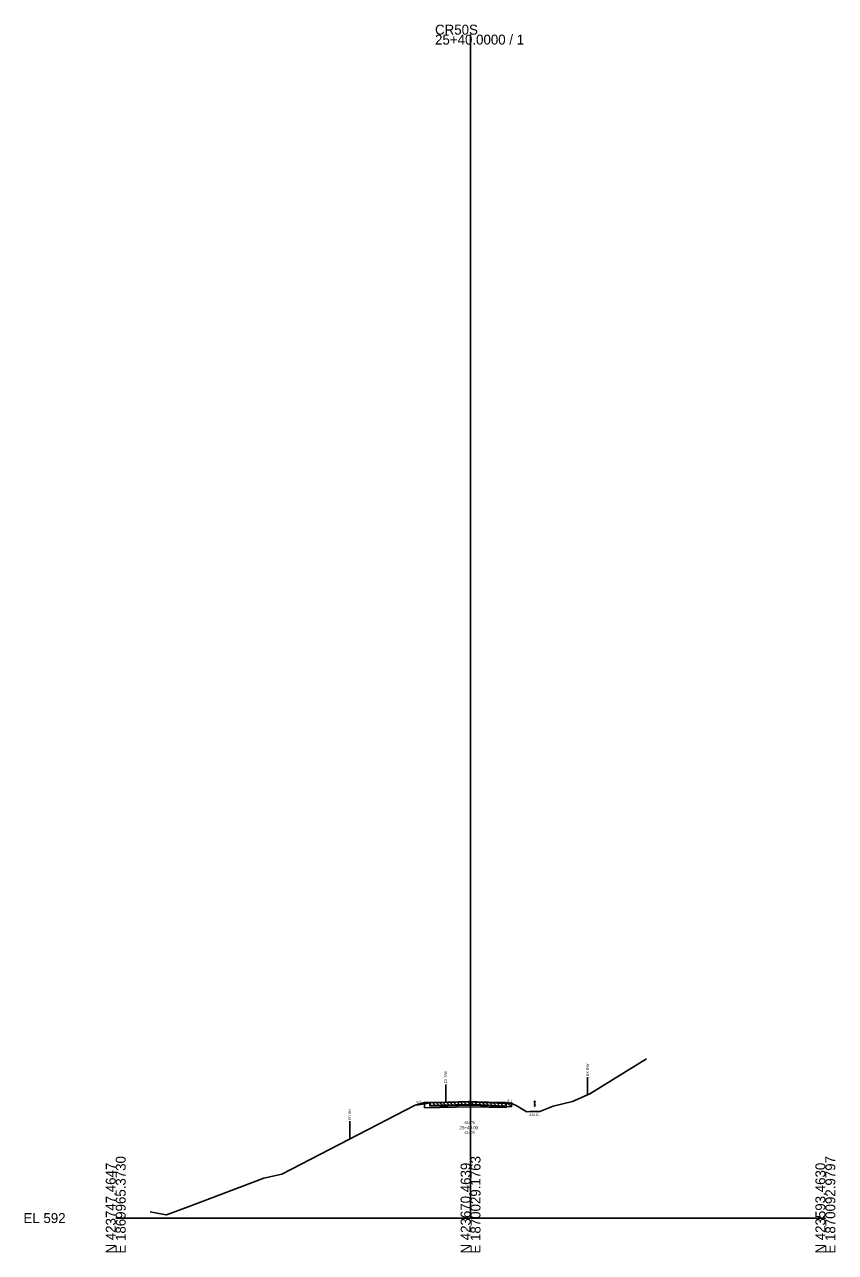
# Model space of a CAD drawing. Extents: x 1866342 to 1870084, y 421982 to 426629.
# Drawn here: x 1867342.4 to 1867571, y 422480.9 to 422827.1 of the extents above; entities that cross this region are included whole.
import ezdxf

# ---------------------------------------------------------------- set-up
doc = ezdxf.new("R2010")
doc.units = 0
for name, color, linetype in [('DR_P_Flow_Arrow', 7, 'Continuous'), ('GK_Cells', 7, 'Continuous'), ('RW_P_Esmt_SH', 7, 'Continuous'), ('RW_X_Fee_RW', 7, 'Continuous'), ('XS_P_Annotation', 7, 'Continuous'), ('XS_P_Earthwork_Shapes', 7, 'Continuous'), ('XS_P_Finished_Grade', 7, 'Continuous'), ('XS_P_Subgrade', 7, 'Continuous'), ('XS_X_Ground_Line', 7, 'Continuous'), ('XS_X_Pavt', 7, 'Continuous')]:
    doc.layers.add(name, color=color, linetype=linetype)

msp = doc.modelspace()

# ---------------------------------------------------------------- linework, layer by layer
at = {"layer": 'DR_P_Flow_Arrow'}
for p, q in [((1867486.09, 422523.31), (1867486.2, 422523.71)), ((1867486.31, 422523.31), (1867486.09, 422523.31)), ((1867486.2, 422523.71), (1867486.31, 422523.31))]:
    msp.add_line(p, q, dxfattribs=at)
msp.add_spline([(1867486.2, 422523.31), (1867486.2, 422523.29), (1867486.16, 422523.13), (1867486.13, 422523.02), (1867486.31, 422522.81), (1867486.1, 422522.57), (1867486.31, 422522.29), (1867486.2, 422522.23), (1867486.2, 422521.96)], degree=3, dxfattribs=at)
at = {"layer": 'GK_Cells'}
for p, q in [((1867468.12, 422490.63), (1867468.12, 422824.29)), ((1867368.12, 422490.63), (1867468.12, 422490.63)), ((1867468.12, 422490.63), (1867568.12, 422490.63))]:
    msp.add_line(p, q, dxfattribs=at)
at = {"layer": 'RW_P_Esmt_SH'}
msp.add_line((1867434.12, 422512.95), (1867434.12, 422517.95), dxfattribs=at)
at = {"layer": 'RW_X_Fee_RW'}
for p, q in [((1867461.12, 422523.28), (1867461.12, 422528.28)), ((1867501.12, 422525.39), (1867501.12, 422530.39))]:
    msp.add_line(p, q, dxfattribs=at)
at = {"layer": 'XS_P_Annotation'}
for q in [(1867455.12, 422523.19), (1867478.12, 422523.23)]:
    msp.add_line((1867468.12, 422523.39), q, dxfattribs=at)
at = {"layer": 'XS_P_Earthwork_Shapes'}
for p, q in [((1867455.12, 422523.19), (1867452.53, 422522.42)), ((1867455.12, 422522.85), (1867455.12, 422523.19)), ((1867455.12, 422522.85), (1867455.12, 422521.75)), ((1867455.12, 422521.75), (1867468.12, 422521.96)), ((1867468.12, 422521.96), (1867478.12, 422521.8)), ((1867479.79, 422522.89), (1867478.12, 422523.23)), ((1867478.12, 422523.23), (1867478.12, 422522.96)), ((1867478.12, 422521.8), (1867478.12, 422522.96)), ((1867478.12, 422522.96), (1867478.12, 422522.22)), ((1867478.12, 422522.96), (1867479.79, 422522.89))]:
    msp.add_line(p, q, dxfattribs=at)
for points in [[(1867452.53, 422522.42), (1867453.49, 422522.6), (1867455.12, 422522.85)], [(1867478.12, 422522.22), (1867468.82, 422522.62), (1867467.55, 422522.68), (1867456.78, 422522.36), (1867456.76, 422523.1), (1867455.12, 422522.85)], [(1867456.76, 422523.1), (1867467.55, 422523.42), (1867478.12, 422522.96)], [(1867456.78, 422522.36), (1867467.55, 422522.68), (1867478.09, 422522.22)]]:
    msp.add_lwpolyline(points, dxfattribs=at)
at = {"layer": 'XS_P_Finished_Grade'}
for p, q in [((1867455.12, 422523.19), (1867452.53, 422522.42)), ((1867478.12, 422523.23), (1867479.79, 422522.89))]:
    msp.add_line(p, q, dxfattribs=at)
at = {"layer": 'XS_P_Subgrade'}
for p, q in [((1867455.12, 422523.19), (1867455.12, 422521.75)), ((1867468.12, 422521.96), (1867455.12, 422521.75)), ((1867468.12, 422521.96), (1867478.12, 422521.8)), ((1867478.12, 422523.23), (1867478.12, 422521.8))]:
    msp.add_line(p, q, dxfattribs=at)
at = {"layer": 'XS_X_Ground_Line'}
msp.add_lwpolyline([(1867377.84, 422492.38), (1867381.77, 422491.67), (1867382.43, 422491.57), (1867388.57, 422493.82), (1867409.84, 422501.89), (1867414.94, 422503.03), (1867428.35, 422509.98), (1867452.53, 422522.42), (1867453.49, 422522.6), (1867456.76, 422523.1), (1867464.03, 422523.29), (1867467.55, 422523.42), (1867468.12, 422523.39), (1867471.23, 422523.27), (1867479.79, 422522.89), (1867480.15, 422522.76), (1867480.96, 422522.39), (1867483.3, 422520.98), (1867484.01, 422520.63), (1867484.83, 422520.64), (1867487.65, 422520.65), (1867491.37, 422522.21), (1867496.82, 422523.51), (1867501.72, 422525.65), (1867517.74, 422535.57)], dxfattribs=at)
at = {"layer": 'XS_X_Pavt'}
for p, q in [((1867456.61, 422523.16), (1867456.61, 422523.41)), ((1867456.61, 422523.16), (1867461.69, 422523.29)), ((1867456.61, 422522.16), (1867456.61, 422523.16)), ((1867456.61, 422522.16), (1867461.69, 422522.29)), ((1867458.41, 422522.21), (1867457.44, 422523.18)), ((1867459.39, 422522.23), (1867458.41, 422523.21)), ((1867460.36, 422522.26), (1867459.39, 422523.23)), ((1867461.33, 422522.29), (1867460.36, 422523.26)), ((1867462.3, 422522.32), (1867461.33, 422523.29)), ((1867461.69, 422523.29), (1867467.53, 422523.51)), ((1867461.69, 422522.29), (1867467.53, 422522.51)), ((1867463.27, 422522.35), (1867462.3, 422523.32)), ((1867464.24, 422522.39), (1867463.27, 422523.35)), ((1867465.2, 422522.42), (1867464.24, 422523.39)), ((1867466.17, 422522.45), (1867465.2, 422523.42)), ((1867467.14, 422522.48), (1867466.17, 422523.45)), ((1867468.14, 422522.48), (1867467.14, 422523.48)), ((1867467.53, 422523.51), (1867468.12, 422523.48)), ((1867467.53, 422522.51), (1867468.12, 422522.48)), ((1867468.12, 422523.48), (1867473.64, 422523.26)), ((1867468.12, 422522.48), (1867473.64, 422522.26)), ((1867469.18, 422522.44), (1867468.14, 422523.48)), ((1867470.23, 422522.4), (1867469.18, 422523.44)), ((1867471.27, 422522.35), (1867470.23, 422523.4)), ((1867472.31, 422522.31), (1867471.27, 422523.35)), ((1867473.36, 422522.27), (1867472.31, 422523.31)), ((1867474.4, 422522.22), (1867473.36, 422523.27)), ((1867473.64, 422523.26), (1867479.63, 422523)), ((1867473.64, 422522.26), (1867479.63, 422522)), ((1867475.45, 422522.18), (1867474.4, 422523.22)), ((1867476.49, 422522.13), (1867475.45, 422523.18)), ((1867477.54, 422522.09), (1867476.49, 422523.13)), ((1867478.58, 422522.04), (1867477.54, 422523.09)), ((1867479.63, 422522), (1867478.58, 422523.04)), ((1867479.63, 422523), (1867479.63, 422523.25)), ((1867479.63, 422522), (1867479.63, 422523))]:
    msp.add_line(p, q, dxfattribs=at)

# ---------------------------------------------------------------- texts
at = {"layer": 'GK_Cells'}
for s, p in [('CR50S', (1867458.12, 422824.29)), ('25+40.0000 / 1', (1867458.12, 422821.49)), ('EL 592', (1867342.12, 422489.23))]:
    msp.add_text(s, height=2.8, dxfattribs=at).set_placement(p)
for s, p in [('E 1869965.3730', (1867370.92, 422480.63)), ('E 1870029.1763', (1867470.92, 422480.63)), ('E 1870092.9797', (1867570.92, 422480.63)), ('N 423747.4647', (1867368.12, 422480.63)), ('N 423670.4639', (1867468.12, 422480.63)), ('N 423593.4630', (1867568.12, 422480.63))]:
    msp.add_text(s, height=2.8, rotation=90, dxfattribs=at).set_placement(p)
at = {"layer": 'RW_P_Esmt_SH'}
msp.add_text('PR SH', height=0.7, rotation=90, dxfattribs=at).set_placement((1867434.47, 422518.3))
at = {"layer": 'RW_X_Fee_RW'}
for p in [(1867461.47, 422528.63), (1867501.47, 422530.74)]:
    msp.add_text('EX R/W', height=0.7, rotation=90, dxfattribs=at).set_placement(p)
at = {"layer": 'XS_P_Annotation'}
for rotation, p in [(16.5299, (1867453.01, 422522.92)), (349.9548, (1867478.44, 422523.42))]:
    msp.add_text('6:1', height=0.7, rotation=rotation, dxfattribs=at).set_placement(p)
for s, height, p in [('624.76', 0.7, (1867466.42, 422517.18)), ('622.01', 0.7, (1867484.71, 422519.39)), ('25+40.00', 0.9, (1867465.01, 422515.68)), ('624.76', 0.7, (1867466.42, 422514.38))]:
    msp.add_text(s, height=height, dxfattribs=at).set_placement(p)

doc.saveas('drawing.dxf')
